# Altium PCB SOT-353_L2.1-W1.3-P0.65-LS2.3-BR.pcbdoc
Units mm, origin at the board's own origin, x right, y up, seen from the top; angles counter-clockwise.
Board outline 15.43 x 15.21 mm, 2 copper layers (Top Layer, Bottom Layer), stack 0 mm thick; 1 components, 0 nets, 5 pads, 0 vias.
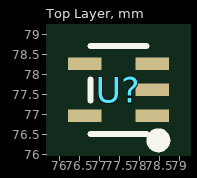
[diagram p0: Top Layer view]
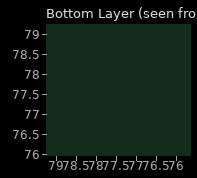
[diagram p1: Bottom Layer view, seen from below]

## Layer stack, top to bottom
Top Layer: signal copper (thickness not stored)
Bottom Layer: signal copper (thickness not stored)

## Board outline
85.276,69.85 69.85,69.85 69.85,85.061 85.276,85.061

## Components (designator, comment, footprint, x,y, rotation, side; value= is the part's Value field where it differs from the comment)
U? "" SOT-353_L2.1-W1.3-P0.65-LS2.3-BR 77.464,77.61 r0 top

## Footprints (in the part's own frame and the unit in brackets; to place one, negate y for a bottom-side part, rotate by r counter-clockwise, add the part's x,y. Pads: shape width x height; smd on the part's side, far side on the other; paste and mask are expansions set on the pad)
SOT-353_L2.1-W1.3-P0.65-LS2.3-BR [mm]
  rect 0.839x0.315 smd: 1(0.844,-0.65) 2(0.844,0) 3(0.844,0.65) 4(-0.844,0.65) 5(-0.844,-0.65)
  silkscreen extent -0.7,-1.41 1.15,1.1

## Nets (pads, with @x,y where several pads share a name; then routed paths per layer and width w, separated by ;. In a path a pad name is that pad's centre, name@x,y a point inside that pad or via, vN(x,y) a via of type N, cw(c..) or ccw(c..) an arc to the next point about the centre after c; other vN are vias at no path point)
pads on no net: U?.1 U?.2 U?.3 U?.4 U?.5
